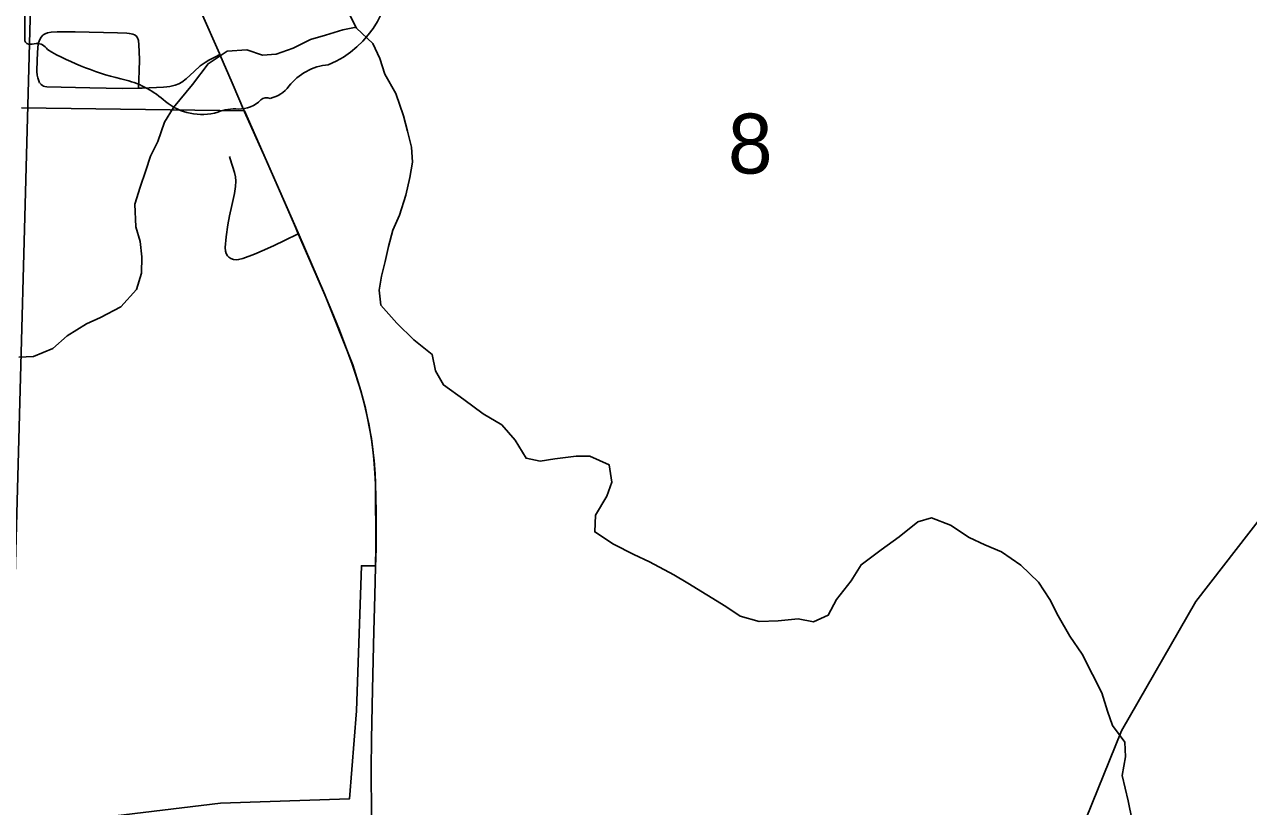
# Model space of a CAD drawing. Extents: x 0 to 34, y 0 to 22.
# Drawn here: x 6.731 to 7.587, y 18.594 to 19.14 of the extents above; entities that cross this region are included whole.
import ezdxf

# ---------------------------------------------------------------- set-up
doc = ezdxf.new("R2010")
doc.units = 0
for name, color, linetype in [('GM_X_City_Street', 7, 'Continuous'), ('GM_X_Corporation', 7, 'Continuous'), ('GM_X_Minor_River', 7, 'Continuous'), ('GM_X_Rail_Line', 7, 'Continuous'), ('GM_X_Section_Text', 7, 'Continuous'), ('GM_X_State_Route', 7, 'Continuous'), ('GM_X_State_Shield', 7, 'Continuous'), ('GM_X_Township_Road', 7, 'Continuous')]:
    doc.layers.add(name, color=color, linetype=linetype)

msp = doc.modelspace()

# ---------------------------------------------------------------- linework, layer by layer
at = {"layer": 'GM_X_City_Street'}
msp.add_lwpolyline([(6.92267, 18.99374), (6.91311, 18.98907), (6.90587, 18.98553), (6.89911, 18.98244), (6.89224, 18.97959), (6.88409, 18.97652), (6.88107, 18.97574), (6.87922, 18.97561), (6.87738, 18.97581), (6.87564, 18.9764), (6.87413, 18.97745), (6.87331, 18.97833), (6.87233, 18.97988), (6.8718, 18.98166), (6.87161, 18.98413), (6.87226, 18.99153), (6.87348, 19.00008), (6.87463, 19.00617), (6.87632, 19.01342), (6.87822, 19.02189), (6.87892, 19.0268), (6.87901, 19.03051), (6.87876, 19.03359), (6.87809, 19.03661), (6.87507, 19.04605), (6.87458, 19.04779)], dxfattribs=at)
at = {"layer": 'GM_X_Corporation'}
for points in [[(6.74716, 19.57625), (6.72002, 18.57343), (5.77565, 18.58596), (5.79735, 19.55844), (5.79814, 19.59794)], [(6.74861, 19.58646), (7.75042, 19.56547), (7.73457, 18.54715), (6.72002, 18.57343), (6.74716, 19.57625)]]:
    msp.add_lwpolyline(points, close=True, dxfattribs=at)
msp.add_lwpolyline([(6.78734, 18.58599), (6.86833, 18.59597), (6.95854, 18.59899), (6.96329, 18.66047), (6.96678, 18.76177), (6.97673, 18.76161), (6.97699, 18.77455), (6.97663, 18.81871), (6.97625, 18.82666), (6.97555, 18.83592), (6.9748, 18.84331), (6.97381, 18.85067), (6.96965, 18.87192), (6.9665, 18.8839), (6.96078, 18.9022), (6.94109, 18.95181), (6.9226, 18.99446), (6.88513, 19.07965), (6.72926, 19.08167)], dxfattribs=at)
at = {"layer": 'GM_X_Minor_River'}
for points in [[(7.28258, 18.7225), (7.27201, 18.7246), (7.25795, 18.72336), (7.24467, 18.72286), (7.23146, 18.72653), (7.22135, 18.73318), (7.20824, 18.74141), (7.19475, 18.74964), (7.185, 18.75552), (7.16811, 18.76458), (7.15721, 18.76972), (7.14294, 18.77683), (7.12983, 18.78544), (7.13044, 18.79719), (7.13828, 18.81032), (7.14188, 18.82012), (7.13984, 18.8323), (7.1263, 18.83826), (7.11683, 18.83844), (7.102, 18.83646), (7.09173, 18.83476), (7.08191, 18.83685), (7.07419, 18.84952), (7.06492, 18.86033), (7.05179, 18.8678), (7.03833, 18.87793), (7.02412, 18.88807), (7.01862, 18.89805), (7.01619, 18.90948), (7.00349, 18.91959), (6.99158, 18.93121), (6.98045, 18.94395), (6.97913, 18.95423), (6.98084, 18.96406), (6.98331, 18.97426), (6.98579, 18.98484), (6.98866, 18.99617), (6.99342, 19.0067), (6.99786, 19.02066), (7.00075, 19.03313), (7.00248, 19.04372), (7.00192, 19.05436), (6.9991, 19.06542), (6.99627, 19.0761), (6.99089, 19.09177), (6.98318, 19.1052), (6.97961, 19.11628), (6.97488, 19.12662), (6.96333, 19.13747), (6.95858, 19.14705)], [(6.96307, 19.13799), (6.95382, 19.13614), (6.94162, 19.13258), (6.93132, 19.12937), (6.91907, 19.12353), (6.90723, 19.11921), (6.89774, 19.11864), (6.88681, 19.12227), (6.87314, 19.1214), (6.8597, 19.11255), (6.8488, 19.09796), (6.8356, 19.0819), (6.82933, 19.07177), (6.82452, 19.0582), (6.8194, 19.04806), (6.81617, 19.03787), (6.81215, 19.02619), (6.80851, 19.01449), (6.80934, 18.99854), (6.81217, 18.98823), (6.81348, 18.97758), (6.81327, 18.9662), (6.80963, 18.95489), (6.79878, 18.94257), (6.7846, 18.93526), (6.77466, 18.9309), (6.76123, 18.92244), (6.75119, 18.91352), (6.73782, 18.90809), (6.72757, 18.90754)], [(7.50516, 18.58383), (7.50239, 18.59755), (7.49818, 18.61509), (7.50071, 18.62832), (7.50015, 18.63858), (7.49165, 18.65013), (7.48805, 18.66006), (7.48413, 18.67305), (7.47755, 18.6857), (7.47024, 18.69988), (7.46176, 18.71257), (7.45369, 18.72677), (7.44785, 18.73827), (7.43973, 18.75019), (7.42745, 18.76219), (7.41398, 18.77157), (7.40232, 18.77635), (7.39142, 18.78149), (7.37831, 18.79009), (7.36514, 18.79528), (7.35561, 18.79243), (7.34251, 18.78206), (7.32982, 18.77282), (7.31597, 18.76246), (7.30892, 18.75121), (7.29881, 18.73813), (7.29291, 18.72723), (7.28258, 18.7225)]]:
    msp.add_lwpolyline(points, dxfattribs=at)
at = {"layer": 'GM_X_Rail_Line'}
msp.add_lwpolyline([(7.42308, 18.14057), (7.43188, 18.44265), (7.44566, 18.50851), (7.46862, 18.57437), (7.49771, 18.64635), (7.54977, 18.73671), (7.59723, 18.79798), (7.66766, 18.8669), (7.75034, 18.93888), (8.02439, 19.18087), (8.41634, 19.53007), (8.51585, 19.59762), (8.7545, 19.71913), (8.85017, 19.77075), (8.9, 19.79567)], dxfattribs=at)
at = {"layer": 'GM_X_State_Route'}
msp.add_line((6.97674, 18.76089), (6.97624, 18.74097), dxfattribs=at)
for points in [[(6.85479, 19.14858), (6.86765, 19.11968), (6.86792, 19.11905), (6.87643, 19.0991), (6.8852, 19.07893)], [(6.8852, 19.07893), (6.89967, 19.04687), (6.91049, 19.02176), (6.91771, 19.00543), (6.92076, 18.99826), (6.92267, 18.99374), (6.92602, 18.98584), (6.94116, 18.95109), (6.94726, 18.93659), (6.9514, 18.92645), (6.95496, 18.91707), (6.96045, 18.9027), (6.96281, 18.89564), (6.96657, 18.88318), (6.96972, 18.8712), (6.97195, 18.86091), (6.97388, 18.84995), (6.97487, 18.84259), (6.97562, 18.8352), (6.97633, 18.82594), (6.97668, 18.81913), (6.97711, 18.79949)], [(6.97711, 18.79949), (6.9772, 18.79557), (6.97706, 18.77384), (6.97674, 18.76089)], [(6.97624, 18.74097), (6.9756, 18.71607), (6.97459, 18.67524), (6.97395, 18.64059), (6.97362, 18.61964), (6.97396, 18.587)]]:
    msp.add_lwpolyline(points, dxfattribs=at)
at = {"layer": 'GM_X_State_Shield'}
msp.add_line((6.73172, 19.32986), (6.73172, 19.12974), dxfattribs=at)
for centre, radius, start, end in [((6.91713, 19.17645), 0.06994, 292.30889, 8.98584), ((6.73477, 19.1293), 0.00308, 171.95839, 258.30661), ((6.73523, 19.14977), 0.02352, 267.33899, 280.60386), ((6.74005, 19.11819), 0.00848, 29.74838, 93.27175), ((6.84711, 19.29799), 0.20192, 240.41292, 257.1985), ((6.94662, 19.07355), 0.0383, 94.40312, 142.57675), ((6.78691, 19.03983), 0.06318, 47.18416, 75.83597), ((6.89809, 19.11034), 0.0226, 282.87319, 323.27711), ((6.88133, 19.10221), 0.02136, 268.77702, 315.54927), ((6.90065, 19.08283), 0.00601, 65.75173, 132.64842), ((6.85524, 19.1172), 0.04009, 230.70037, 286.29184), ((6.8784, 19.04801), 0.03294, 85.69512, 111.20995)]:
    msp.add_arc(centre, radius, start, end, dxfattribs=at)
at = {"layer": 'GM_X_Township_Road'}
for points in [[(6.74204, 19.09917), (6.74175, 19.09993), (6.74116, 19.10125), (6.74067, 19.1028), (6.74033, 19.10448), (6.74009, 19.10723), (6.74027, 19.11532), (6.74078, 19.12402), (6.7413, 19.12708), (6.74212, 19.12944), (6.74305, 19.13104), (6.74431, 19.1324), (6.74501, 19.13293), (6.74586, 19.13344), (6.7476, 19.13412), (6.75004, 19.13458), (6.75438, 19.13475), (6.76682, 19.13482), (6.79648, 19.13422), (6.80289, 19.13398), (6.80462, 19.13376), (6.80596, 19.13349), (6.80725, 19.13317), (6.80833, 19.13272), (6.80937, 19.13207), (6.81048, 19.13063), (6.81103, 19.12886), (6.8114, 19.12577), (6.81171, 19.11579), (6.8116, 19.10708), (6.8114, 19.10211), (6.81113, 19.09541), (6.79998, 19.09516), (6.77701, 19.09571), (6.74715, 19.09652), (6.7457, 19.09665), (6.74472, 19.09697), (6.74393, 19.09743), (6.7432, 19.09803), (6.74226, 19.09886)], [(6.81113, 19.09541), (6.81366, 19.09546), (6.82858, 19.09613), (6.83094, 19.09632), (6.83304, 19.09665), (6.83671, 19.0975), (6.83916, 19.09841), (6.84144, 19.09972), (6.84443, 19.10211), (6.84994, 19.10718), (6.85428, 19.11112), (6.85759, 19.11344), (6.86023, 19.11493), (6.86486, 19.11742), (6.86792, 19.11905)]]:
    msp.add_lwpolyline(points, dxfattribs=at)

# ---------------------------------------------------------------- texts
at = {"layer": 'GM_X_Section_Text'}
msp.add_text('8', height=0.04186, rotation=0.00001, dxfattribs=at).set_placement((7.22289, 19.03582))

doc.saveas('drawing.dxf')
